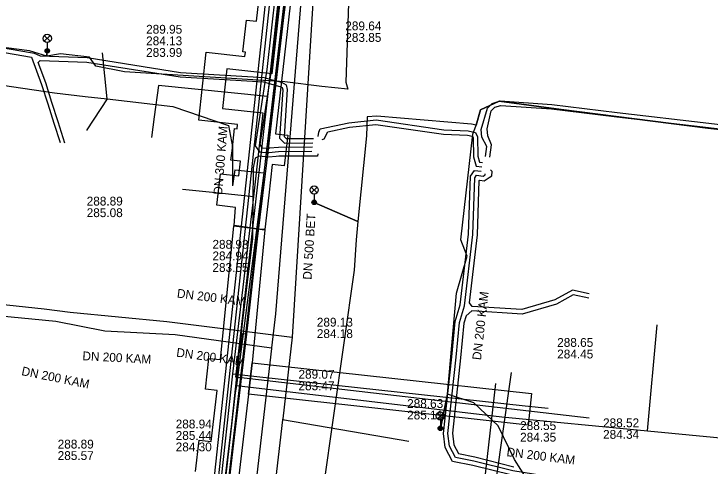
# Model space of a CAD drawing. Extents: x -595540 to -593988, y -1160850 to -1159202.
# Drawn here: x -594329 to -594265.8, y -1160378.8 to -1160337.8 of the extents above; entities that cross this region are included whole.
import ezdxf

# ---------------------------------------------------------------- set-up
doc = ezdxf.new("R2010")
doc.units = 0
for name, color, linetype in [('BVK-DESTOVA_popisy', 7, 'Continuous'), ('BVK-DESTOVA_trasa sítě', 7, 'Continuous'), ('BVK-SPLASKOVA_popisy', 7, 'Continuous'), ('BVK-SPLASKOVA_trasa sítě', 7, 'Continuous'), ('BVK-VODOVOD_trasa sítě', 7, 'Continuous'), ('BVK-VODOVOD_trasa zrušené sítě', 7, 'Continuous'), ('CETIN_kabel podzemní', 7, 'Continuous'), ('DESTOVA-NEPROVOZOVANA_popisy', 7, 'Continuous'), ('DESTOVA_trasa neprovozované sítě', 7, 'Continuous'), ('EON-NN_kabel', 7, 'Continuous'), ('EON-VN_kabel', 7, 'Continuous'), ('PODA_kabel optický', 7, 'Continuous'), ('SPLASKOVA_neprovozovaná  trasa sítě', 7, 'Continuous'), ('SPLASKOVA_popisy neprovozované sítě', 7, 'Continuous'), ('TEPLARNY-TEPLOVODY_trasa sítě', 7, 'Continuous'), ('TSB_kabel VO', 7, 'Continuous'), ('TSB_kolektor', 7, 'Continuous'), ('TSB_lampy VO', 7, 'Continuous')]:
    doc.layers.add(name, color=color, linetype=linetype)

msp = doc.modelspace()

# ---------------------------------------------------------------- linework, layer by layer
at = {"layer": 'BVK-DESTOVA_popisy'}
for p, q in [((-594298.9, -1160339.377), (-594298.9, -1160339.377)), ((-594316.971, -1160340.21), (-594316.971, -1160340.21)), ((-594310.954, -1160359.709), (-594310.954, -1160359.709)), ((-594303.149, -1160370.966), (-594303.149, -1160370.966)), ((-594283.039, -1160375.621), (-594283.039, -1160375.621)), ((-594275.512, -1160375.366), (-594275.512, -1160375.366))]:
    msp.add_line(p, q, dxfattribs=at)
at = {"layer": 'BVK-DESTOVA_trasa sítě'}
for p in [(-594301.602, -1160332.815), (-594315.086, -1160365.649)]:
    msp.add_line(p, (-594303.711, -1160367.066), dxfattribs=at)
msp.add_lwpolyline([(-594303.711, -1160367.066), (-594304.575, -1160374.476), (-594304.585, -1160374.568), (-594307.592, -1160400.363)], dxfattribs=at)
at = {"layer": 'BVK-SPLASKOVA_popisy'}
msp.add_line((-594301.483, -1160365.318), (-594301.483, -1160365.318), dxfattribs=at)
at = {"layer": 'BVK-SPLASKOVA_trasa sítě'}
msp.add_line((-594302.518, -1160331.435), (-594305.229, -1160364.955), dxfattribs=at)
msp.add_lwpolyline([(-594305.229, -1160364.955), (-594305.586, -1160368.04), (-594305.595, -1160368.114), (-594310.425, -1160409.765)], dxfattribs=at)
at = {"layer": 'BVK-VODOVOD_trasa sítě'}
for points in [[(-594309.64, -1160382.12), (-594308.94, -1160376.17), (-594308.27, -1160370.33), (-594307.84, -1160366.81), (-594307.54, -1160364.15), (-594306.87, -1160358.17), (-594306.15, -1160352.26), (-594305.91, -1160350.26), (-594305.21, -1160344.29), (-594304.5, -1160338.36), (-594303.79, -1160332.42), (-594303.14, -1160326.47), (-594302.47, -1160320.51), (-594301.703, -1160314.009), (-594301.63, -1160313.38), (-594301.561, -1160312.779), (-594300.29, -1160301.73)], [(-594307.84, -1160366.81), (-594308.243, -1160366.764), (-594308.27, -1160367.03), (-594308.43, -1160368.45)]]:
    msp.add_lwpolyline(points, dxfattribs=at)
at = {"layer": 'BVK-VODOVOD_trasa zrušené sítě'}
msp.add_lwpolyline([(-594301.608, -1160312.73), (-594301.73, -1160313.43), (-594306.08, -1160350.36), (-594307.98, -1160367.06), (-594311.9, -1160400.22), (-594312.26, -1160403.13), (-594312.57, -1160405.62)], dxfattribs=at)
at = {"layer": 'CETIN_kabel podzemní'}
for points in [[(-594300.85, -1160308.27), (-594306.29, -1160352.19)], [(-594320.52, -1160345.47), (-594320.928, -1160341.308)], [(-594342.33, -1160342.42), (-594325.27, -1160344.92), (-594322.49, -1160345.24), (-594320.52, -1160345.47)], [(-594320.52, -1160345.47), (-594322.35, -1160348.28), (-594322.36, -1160348.33)], [(-594320.52, -1160345.47), (-594314.54, -1160346.17), (-594309.5, -1160347.87), (-594309.13, -1160349.83), (-594309.14, -1160352.13), (-594309.14, -1160353.35)], [(-594308.91, -1160351.89), (-594309.14, -1160353.35)], [(-594308.91, -1160351.89), (-594306.29, -1160352.19)], [(-594306.29, -1160352.19), (-594308.76, -1160371.46)], [(-594271.483, -1160375.58), (-594270.595, -1160365.955)], [(-594308.76, -1160371.46), (-594308.9, -1160372.12)], [(-594308.76, -1160371.46), (-594284.69, -1160374.31)], [(-594308.9, -1160372.12), (-594309.88, -1160380.89)], [(-594284.69, -1160374.31), (-594271.483, -1160375.58)], [(-594271.483, -1160375.58), (-594251.947, -1160377.458)]]:
    msp.add_lwpolyline(points, dxfattribs=at)
at = {"layer": 'DESTOVA-NEPROVOZOVANA_popisy'}
for p, q in [((-594322.363, -1160356.191), (-594322.363, -1160356.191)), ((-594279.675, -1160369.006), (-594279.675, -1160369.006))]:
    msp.add_line(p, q, dxfattribs=at)
at = {"layer": 'DESTOVA_trasa neprovozované sítě'}
for p, q in [((-594346.727, -1160362.337), (-594326.209, -1160364.512)), ((-594326.209, -1160364.512), (-594323.877, -1160364.801)), ((-594323.877, -1160364.801), (-594315.086, -1160365.649)), ((-594283.848, -1160370.271), (-594285.288, -1160380.333)), ((-594293.149, -1160376.551), (-594304.585, -1160374.568))]:
    msp.add_line(p, q, dxfattribs=at)
at = {"layer": 'EON-NN_kabel'}
for points in [[(-594303.178, -1160320.809), (-594303.187, -1160320.826), (-594303.266, -1160321.275), (-594303.27, -1160321.296), (-594303.434, -1160321.876), (-594303.393, -1160323.479), (-594304.047, -1160328.805), (-594305.613, -1160342.862), (-594305.737, -1160343.669), (-594305.798, -1160344.067), (-594306.653, -1160349.62), (-594306.462, -1160349.897), (-594305.86, -1160349.954), (-594305.815, -1160349.95), (-594305.776, -1160349.947)], [(-594303.703, -1160321.36), (-594303.819, -1160321.767), (-594303.794, -1160323.448), (-594304.445, -1160328.759), (-594306.009, -1160342.81), (-594306.125, -1160343.561), (-594306.186, -1160343.958), (-594307.073, -1160349.716), (-594306.686, -1160350.277), (-594305.857, -1160350.356), (-594305.823, -1160350.353)], [(-594332.766, -1160340.369), (-594327.473, -1160341.269), (-594327.116, -1160341.327), (-594326.573, -1160341.576), (-594322.316, -1160341.73), (-594313.842, -1160343.079), (-594306.257, -1160343.524), (-594306.125, -1160343.561), (-594305.737, -1160343.669), (-594304.685, -1160343.964), (-594304.275, -1160344.183), (-594304.171, -1160344.619), (-594304.458, -1160348.874), (-594304.261, -1160349.072), (-594301.8, -1160349.054)], [(-594332.818, -1160340.765), (-594327.36, -1160341.694), (-594326.454, -1160344.157), (-594325.894, -1160345.92), (-594325.342, -1160347.677), (-594324.782, -1160349.418)], [(-594324.346, -1160349.474), (-594324.96, -1160347.555), (-594325.512, -1160345.8), (-594326.076, -1160344.027), (-594326.758, -1160342.171), (-594326.587, -1160341.976), (-594322.354, -1160342.128), (-594313.886, -1160343.477), (-594306.323, -1160343.92), (-594306.186, -1160343.958), (-594305.798, -1160344.067), (-594304.835, -1160344.338), (-594304.623, -1160344.451), (-594304.575, -1160344.653), (-594304.87, -1160349.027), (-594304.428, -1160349.472), (-594301.843, -1160349.453)], [(-594286.191, -1160350.702), (-594286.061, -1160349.786), (-594286.502, -1160348.957), (-594286.568, -1160348.242), (-594286.009, -1160346.326), (-594285.561, -1160345.878), (-594284.845, -1160345.652), (-594280.155, -1160345.972), (-594274.228, -1160346.715), (-594265.909, -1160347.666), (-594258.069, -1160348.616), (-594249.195, -1160349.865), (-594241.282, -1160351.392), (-594232.419, -1160352.474), (-594223.153, -1160353.822), (-594216.811, -1160354.238), (-594214.024, -1160354.304), (-594209.023, -1160355.021), (-594208.842, -1160355.267), (-594208.916, -1160356.63), (-594209.727, -1160360.059), (-594209.827, -1160360.621), (-594210.906, -1160361.362), (-594213.588, -1160361.166)], [(-594285.794, -1160350.751), (-594285.622, -1160349.642), (-594285.971, -1160348.823), (-594286.029, -1160348.196), (-594285.665, -1160346.548), (-594285.347, -1160346.23), (-594284.797, -1160346.056), (-594280.193, -1160346.37), (-594274.276, -1160347.113), (-594265.955, -1160348.064), (-594258.121, -1160349.012), (-594249.261, -1160350.259), (-594241.344, -1160351.788), (-594232.473, -1160352.87), (-594223.195, -1160354.22), (-594216.829, -1160354.638), (-594214.058, -1160354.704), (-594209.451, -1160355.364), (-594209.259, -1160355.556), (-594209.314, -1160356.572), (-594210.119, -1160359.977), (-594210.192, -1160360.386), (-594211.015, -1160360.953), (-594213.551, -1160360.768)], [(-594301.36, -1160348.885), (-594301.316, -1160348.481), (-594301.177, -1160348.195), (-594298.593, -1160347.645), (-594296.112, -1160347.381), (-594289.947, -1160348.28), (-594287.751, -1160348.366), (-594287.1, -1160348.506), (-594286.915, -1160348.916), (-594286.876, -1160350.651), (-594286.709, -1160351.211), (-594286.461, -1160351.246)], [(-594301.006, -1160349.148), (-594300.818, -1160349.094), (-594300.495, -1160348.458), (-594298.531, -1160348.041), (-594296.12, -1160347.785), (-594289.985, -1160348.679), (-594287.801, -1160348.764), (-594287.382, -1160348.854), (-594287.313, -1160349.006), (-594287.274, -1160350.713), (-594287.021, -1160351.569), (-594286.511, -1160351.642)], [(-594301.886, -1160349.854), (-594304.971, -1160349.876), (-594305.776, -1160349.947)], [(-594301.929, -1160350.254), (-594304.96, -1160350.277), (-594305.823, -1160350.353)], [(-594301.381, -1160350.441), (-594301.415, -1160350.662), (-594304.924, -1160350.675), (-594305.158, -1160350.695)], [(-594305.158, -1160350.695), (-594305.86, -1160350.757), (-594306.724, -1160350.675), (-594307.07, -1160350.839), (-594307.256, -1160351.713), (-594307.328, -1160358.121), (-594308.265, -1160365.813), (-594309.231, -1160374.948), (-594310.219, -1160383.198), (-594311.547, -1160392.656), (-594311.644, -1160394.073), (-594311.66, -1160394.307), (-594311.805, -1160396.436), (-594311.807, -1160396.47), (-594311.946, -1160398.506), (-594312.687, -1160405.401), (-594313.104, -1160407.179)], [(-594283.774, -1160379.603), (-594287.316, -1160378.721), (-594289.17, -1160378.348), (-594289.827, -1160377.068), (-594289.985, -1160375.8), (-594289.242, -1160368.861), (-594288.923, -1160365.664), (-594288.472, -1160364.157), (-594287.718, -1160357.723), (-594287.552, -1160352.479), (-594287.163, -1160351.952), (-594286.56, -1160352.04)], [(-594257.949, -1160391.833), (-594262.324, -1160394.761), (-594274.031, -1160394.098), (-594274.689, -1160394.195), (-594275.086, -1160393.889), (-594275.413, -1160393.637), (-594275.378, -1160393.013), (-594274.087, -1160381.281), (-594274.304, -1160380.926), (-594276.966, -1160380.275), (-594283.694, -1160379.211), (-594287.228, -1160378.331), (-594288.902, -1160377.994), (-594289.439, -1160376.948), (-594289.582, -1160375.797), (-594288.844, -1160368.902), (-594288.529, -1160365.742), (-594288.079, -1160364.239), (-594287.319, -1160357.753), (-594287.156, -1160352.617), (-594286.984, -1160352.384), (-594286.377, -1160352.471), (-594286.22, -1160352.37), (-594286.203, -1160352.262)], [(-594276.765, -1160363.156), (-594278.293, -1160362.817), (-594279.893, -1160363.702), (-594282.892, -1160364.578), (-594287.387, -1160364.289), (-594287.643, -1160363.955), (-594286.92, -1160357.783), (-594286.764, -1160352.885), (-594286.694, -1160352.83), (-594286.286, -1160352.888), (-594285.854, -1160352.61), (-594285.619, -1160352.451), (-594285.568, -1160352.069), (-594285.736, -1160351.9)], [(-594276.81, -1160363.555), (-594278.231, -1160363.241), (-594279.739, -1160364.074), (-594282.848, -1160364.982), (-594287.413, -1160364.689), (-594287.935, -1160365.152), (-594288.135, -1160365.82), (-594288.446, -1160368.943), (-594289.179, -1160375.794), (-594289.051, -1160376.828), (-594288.634, -1160377.64), (-594287.14, -1160377.941), (-594283.614, -1160378.819)]]:
    msp.add_lwpolyline(points, dxfattribs=at)
at = {"layer": 'EON-VN_kabel'}
for points in [[(-594311.232, -1160405.064), (-594313.094, -1160404.864), (-594304.202, -1160322.43), (-594304.158, -1160322.02), (-594303.38, -1160314.81), (-594302.494, -1160314.925), (-594302.392, -1160314.132), (-594302.341, -1160313.736), (-594296.713, -1160270.069), (-594284.742, -1160163.314), (-594284.697, -1160162.913), (-594284.36, -1160159.91), (-594283.302, -1160160.01)], [(-594311.292, -1160405.459), (-594313.533, -1160405.218), (-594304.61, -1160322.488), (-594304.565, -1160322.078), (-594303.733, -1160314.361), (-594302.896, -1160314.469), (-594302.844, -1160314.074), (-594302.791, -1160313.678), (-594297.011, -1160270.069), (-594285.141, -1160163.214)]]:
    msp.add_lwpolyline(points, dxfattribs=at)
at = {"layer": 'PODA_kabel optický'}
for points in [[(-594298.883, -1160281.099), (-594305.951, -1160345.267)], [(-594305.951, -1160345.267), (-594315.842, -1160344.262), (-594316.248, -1160347.087)], [(-594305.951, -1160345.267), (-594308.872, -1160370.712)], [(-594316.248, -1160347.087), (-594316.48, -1160348.98)], [(-594276.76, -1160374.407), (-594308.872, -1160370.712)]]:
    msp.add_lwpolyline(points, dxfattribs=at)
at = {"layer": 'SPLASKOVA_neprovozovaná  trasa sítě'}
for p, q in [((-594342.163, -1160364.037), (-594325.173, -1160365.615)), ((-594325.173, -1160365.615), (-594320.71, -1160366.515)), ((-594320.71, -1160366.515), (-594314.338, -1160366.843)), ((-594314.338, -1160366.843), (-594305.586, -1160368.04)), ((-594285.282, -1160371.264), (-594286.362, -1160380.817))]:
    msp.add_line(p, q, dxfattribs=at)
at = {"layer": 'SPLASKOVA_popisy neprovozované sítě'}
for p, q in [((-594293.29, -1160372.697), (-594293.29, -1160372.697)), ((-594314.287, -1160374.551), (-594314.287, -1160374.551)), ((-594324.995, -1160376.374), (-594324.995, -1160376.374))]:
    msp.add_line(p, q, dxfattribs=at)
at = {"layer": 'TEPLARNY-TEPLOVODY_trasa sítě'}
for p, q in [((-594310.356, -1160354.024), (-594313.681, -1160353.679)), ((-594307.215, -1160354.35), (-594310.356, -1160354.024)), ((-594309.123, -1160370.406), (-594282.585, -1160373.29)), ((-594282.585, -1160373.29), (-594280.487, -1160373.518))]:
    msp.add_line(p, q, dxfattribs=at)
for points in [[(-594301.777, -1160308.985), (-594303.702, -1160326.332), (-594305.572, -1160343.192), (-594309.637, -1160342.741), (-594310.036, -1160346.338), (-594306.371, -1160346.745), (-594307.215, -1160354.35)], [(-594307.215, -1160354.35), (-594308.188, -1160362.543), (-594309.123, -1160370.406)], [(-594309.123, -1160370.406), (-594310.325, -1160381.235), (-594314.108, -1160380.816), (-594314.504, -1160384.391), (-594310.788, -1160384.804), (-594311.848, -1160394.284), (-594312.897, -1160403.662), (-594315.942, -1160403.281)]]:
    msp.add_lwpolyline(points, dxfattribs=at)
at = {"layer": 'TSB_kabel VO'}
for points in [[(-594251.443, -1160326.554), (-594268.283, -1160324.665), (-594269.954, -1160324.73), (-594273.18, -1160324.357), (-594291.308, -1160321.949), (-594294.695, -1160321.833), (-594295.72, -1160321.71), (-594296.392, -1160321.841), (-594296.656, -1160324.243), (-594297.827, -1160329.111), (-594298.62, -1160336.827), (-594298.845, -1160343.966), (-594298.677, -1160344.592), (-594301.041, -1160344.344), (-594304.371, -1160343.918), (-594318.941, -1160343.005), (-594321.522, -1160342.512), (-594322.115, -1160341.698), (-594324.732, -1160341.382), (-594325.983, -1160341.602), (-594325.942, -1160341.112), (-594325.983, -1160341.602), (-594327.555, -1160341.113), (-594343.576, -1160339.066)], [(-594215.09, -1160354.558), (-594221.198, -1160354.153), (-594238.219, -1160351.767), (-594248.845, -1160350.075), (-594251.016, -1160349.822), (-594266.02, -1160348.119), (-594279.322, -1160346.441), (-594284.927, -1160345.681), (-594286.645, -1160346.46), (-594287.03, -1160347.86), (-594287.46, -1160347.75), (-594296.05, -1160347.04), (-594296.91, -1160347.1), (-594296.968, -1160348.808), (-594297.765, -1160356.574), (-594301.724, -1160354.853), (-594297.765, -1160356.574), (-594297.903, -1160358.264), (-594298.083, -1160361.004), (-594300.912, -1160380.773)], [(-594282.41, -1160379.995), (-594283.538, -1160378.184), (-594285.028, -1160375.116), (-594287.252, -1160373.024), (-594289.622, -1160372.234), (-594290.275, -1160375.346), (-594289.622, -1160372.234), (-594288.82, -1160363.089), (-594287.84, -1160359.747), (-594288.404, -1160358.241), (-594287.323, -1160348.685), (-594287.03, -1160347.86), (-594286.645, -1160346.46), (-594284.927, -1160345.681), (-594279.322, -1160346.441), (-594266.02, -1160348.119), (-594251.015, -1160349.822), (-594248.845, -1160350.075), (-594238.219, -1160351.767), (-594221.198, -1160354.153), (-594215.089, -1160354.558)]]:
    msp.add_lwpolyline(points, dxfattribs=at)
at = {"layer": 'TSB_kolektor'}
for points in [[(-594301.333, -1160314.385), (-594305.219, -1160348.629), (-594304.128, -1160348.751), (-594304.439, -1160351.534), (-594305.535, -1160351.411), (-594305.85, -1160354.195), (-594306.213, -1160357.312), (-594306.71, -1160357.27), (-594308.994, -1160356.957), (-594308.855, -1160355.307), (-594310.541, -1160355.119), (-594310.223, -1160352.257), (-594308.55, -1160352.443), (-594308.401, -1160351.131), (-594309.282, -1160351.033), (-594309.16, -1160350.17), (-594308.963, -1160348.171), (-594308.718, -1160348.198), (-594308.673, -1160347.781), (-594312.197, -1160347.391), (-594311.514, -1160341.248), (-594308.001, -1160341.638), (-594307.955, -1160341.22), (-594308.187, -1160341.194), (-594307.869, -1160338.332), (-594306.96, -1160338.433), (-594303.825, -1160310.801)], [(-594312.484, -1160379.269), (-594312.163, -1160376.407), (-594311.081, -1160376.528), (-594310.532, -1160371.899), (-594311.597, -1160371.779), (-594311.285, -1160368.997), (-594310.229, -1160369.115), (-594309.014, -1160356.976), (-594306.213, -1160357.351), (-594307.363, -1160369.393), (-594307.675, -1160372.256), (-594311.239, -1160402.348)]]:
    msp.add_lwpolyline(points, dxfattribs=at)
msp.add_lwpolyline([(-594307.363, -1160369.393), (-594282.001, -1160372.19), (-594282.317, -1160375.053), (-594307.675, -1160372.256)], close=True, dxfattribs=at)
at = {"layer": 'TSB_lampy VO'}
for p, q in [((-594326.207, -1160340.252), (-594325.677, -1160339.722)), ((-594326.207, -1160339.722), (-594325.677, -1160340.252)), ((-594326.207, -1160340.252), (-594325.677, -1160339.722)), ((-594326.207, -1160339.722), (-594325.677, -1160340.252)), ((-594325.942, -1160340.362), (-594325.942, -1160341.112)), ((-594325.942, -1160340.362), (-594325.942, -1160341.112)), ((-594301.989, -1160353.993), (-594301.459, -1160353.463)), ((-594301.989, -1160353.463), (-594301.459, -1160353.993)), ((-594301.989, -1160353.993), (-594301.459, -1160353.463)), ((-594301.989, -1160353.463), (-594301.459, -1160353.993)), ((-594301.724, -1160354.103), (-594301.724, -1160354.853)), ((-594301.724, -1160354.103), (-594301.724, -1160354.853)), ((-594290.54, -1160374.486), (-594290.01, -1160373.956)), ((-594290.54, -1160373.956), (-594290.01, -1160374.486)), ((-594290.54, -1160374.486), (-594290.01, -1160373.956)), ((-594290.54, -1160373.956), (-594290.01, -1160374.486)), ((-594290.275, -1160374.596), (-594290.275, -1160375.346)), ((-594290.275, -1160374.596), (-594290.275, -1160375.346))]:
    msp.add_line(p, q, dxfattribs=at)
for centre, radius in [((-594325.942, -1160339.987), 0.375), ((-594325.942, -1160339.987), 0.375), ((-594325.942, -1160341.112), 0.2), ((-594325.942, -1160341.112), 0.2), ((-594325.942, -1160341.112), 0.145), ((-594325.942, -1160341.112), 0.145), ((-594325.942, -1160341.112), 0.0876), ((-594325.942, -1160341.112), 0.0876), ((-594301.724, -1160353.728), 0.375), ((-594301.724, -1160353.728), 0.375), ((-594301.724, -1160354.853), 0.2), ((-594301.724, -1160354.853), 0.2), ((-594301.724, -1160354.853), 0.145), ((-594301.724, -1160354.853), 0.145), ((-594301.724, -1160354.853), 0.0876), ((-594301.724, -1160354.853), 0.0876), ((-594290.275, -1160374.221), 0.375), ((-594290.275, -1160374.221), 0.375), ((-594290.275, -1160375.346), 0.2), ((-594290.275, -1160375.346), 0.2), ((-594290.275, -1160375.346), 0.145), ((-594290.275, -1160375.346), 0.145), ((-594290.275, -1160375.346), 0.0876), ((-594290.275, -1160375.346), 0.0876)]:
    msp.add_circle(centre, radius, dxfattribs=at)

# ---------------------------------------------------------------- texts
at = {"layer": 'BVK-DESTOVA_popisy'}
for s, p in [('289.64', (-594298.9, -1160339.252)), ('289.95', (-594316.971, -1160339.56)), ('284.13', (-594316.971, -1160340.61)), ('283.85', (-594298.9, -1160340.302)), ('283.99', (-594316.971, -1160341.66)), ('288.93', (-594310.954, -1160359.059)), ('284.94', (-594310.954, -1160360.109)), ('283.55', (-594310.954, -1160361.159)), ('289.07', (-594303.149, -1160370.841)), ('283.47', (-594303.149, -1160371.891)), ('288.52', (-594275.512, -1160375.241)), ('288.55', (-594283.039, -1160375.496)), ('284.35', (-594283.039, -1160376.546)), ('284.34', (-594275.512, -1160376.291))]:
    msp.add_text(s, height=0.8, dxfattribs=at).set_placement(p)
for s, rotation, p in [('DN 500 BET', 86.45933, (-594301.962, -1160361.885)), ('DN 200 KAM', 352.89916, (-594314.208, -1160363.475)), ('DN 200 KAM', 352.87498, (-594284.302, -1160377.856))]:
    msp.add_text(s, height=0.8, rotation=rotation, dxfattribs=at).set_placement(p)
at = {"layer": 'BVK-SPLASKOVA_popisy'}
msp.add_text('DN 300 KAM', height=0.8, rotation=85.37071, dxfattribs=at).set_placement((-594310.076, -1160354.196))
for s, p in [('289.13', (-594301.483, -1160366.118)), ('284.18', (-594301.483, -1160367.158))]:
    msp.add_text(s, height=0.8, dxfattribs=at).set_placement(p)
at = {"layer": 'DESTOVA-NEPROVOZOVANA_popisy'}
for s, p in [('288.89', (-594322.363, -1160355.141)), ('285.08', (-594322.363, -1160356.191)), ('288.65', (-594279.675, -1160367.956)), ('284.45', (-594279.675, -1160369.006))]:
    msp.add_text(s, height=0.8, dxfattribs=at).set_placement(p)
at = {"layer": 'SPLASKOVA_popisy neprovozované sítě'}
for rotation, p in [(83.5499, (-594286.591, -1160369.185)), (352.21068, (-594314.267, -1160368.838)), (357.05329, (-594322.764, -1160369.164)), (348.59875, (-594328.324, -1160370.512))]:
    msp.add_text('DN 200 KAM', height=0.8, rotation=rotation, dxfattribs=at).set_placement(p)
for s, p in [('288.63', (-594293.29, -1160373.497)), ('285.11', (-594293.29, -1160374.537)), ('288.94', (-594314.287, -1160375.351)), ('285.44', (-594314.287, -1160376.391)), ('288.89', (-594324.995, -1160377.174)), ('284.30', (-594314.287, -1160377.431)), ('285.57', (-594324.995, -1160378.214))]:
    msp.add_text(s, height=0.8, dxfattribs=at).set_placement(p)

doc.saveas('drawing.dxf')
